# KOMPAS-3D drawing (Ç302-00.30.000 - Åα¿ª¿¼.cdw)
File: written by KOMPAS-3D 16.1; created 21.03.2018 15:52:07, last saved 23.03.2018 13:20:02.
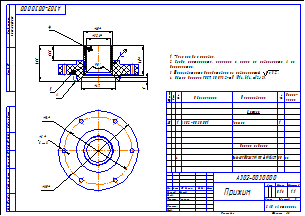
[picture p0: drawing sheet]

Sheet 1: A3, landscape

Title block, sheet 1: name: Прижим; designation: А302-00.30.000; mass: 0,16; scale: 1:1; sheets: 1; organisation: ЗАО «Астерион»; sheet format: A3; stored path: Z:\Мембранные насосы\Мембранный электропривод\А302-00.00.000 - ASTRA-302 (МЭ200)\Чертежи\А302-00.30.000 - Прижим.cdw; drawn by: Милов; technical control: Лучихин

Views: Вид 1, Местный разрез 1, Вид:1, Проекционный вид 2
Referenced files in Z:\Мембранные насосы\Мембранный электропривод\А302-00.00.000 - ASTRA-302 (МЭ200)\3Д\: А302-00.30.000 - Прижим.a3d, А302-00.30.001 - Прижим.m3d
Referenced files in Z:\1 ПКИ 3D\Полипропиленовые фитинги, трубы\: Труба ф40х3,7 (PN10) FV PPR ф. FV PLAST.m3d
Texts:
  *Размеры для справок.
  Следы инструмента, царапины и риски на поверхности А не
  допускаются.
  Шероховатость дорабатываемых поверхностей  Ra 3,2 .
  Общие допуски ГОСТ 30893.2-mK (H14, h14,  t2/2).
  Труба ф40х3,7 (PN10) FV PPR ф. FV PLAST
Dimensions and other numbers on the sheet: 20,5; 49,5; 40; 32,6; 47; 5; 41; 1; 4; 110; 94; 6; 6 отв.; 1:1; 0,16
